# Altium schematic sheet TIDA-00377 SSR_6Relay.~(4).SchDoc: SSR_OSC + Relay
size 431 x 279 mm; Date: Not shown in title block; ApprovedBy: Not shown in title block; CheckedBy: Not shown in title block; Author: Not shown in title block; CompanyName: Not shown in title block; DrawnBy: Jarrod Krebs; Engineer: Not shown in title block; Organization: Not shown in title block; Address1: Not shown in title block; Address2: Not shown in title block; Address3: Not shown in title block; Address4: Not shown in title block; DocumentNumber: 1; Revision: Use project parameter SCH_Rev; SheetNumber: 2; SheetTotal: 3; PageSetup: Record=PageOptions¦CenterHorizontal=True¦CenterVertical=True¦PrintScale=0.62¦XCorrection=1.00¦YCorrection=1.00¦PrintKind=0¦BorderSize=5000000¦LeftOffset=0¦BottomOffset=0¦Orientation=2¦PaperLength=1000¦PaperWidth=1000¦Scale=100¦PaperSource=15¦PrintQuality=-3¦MediaType=1¦DitherType=10¦PrintScaleMode=1¦PaperKind=Letter¦PaperIndex=1
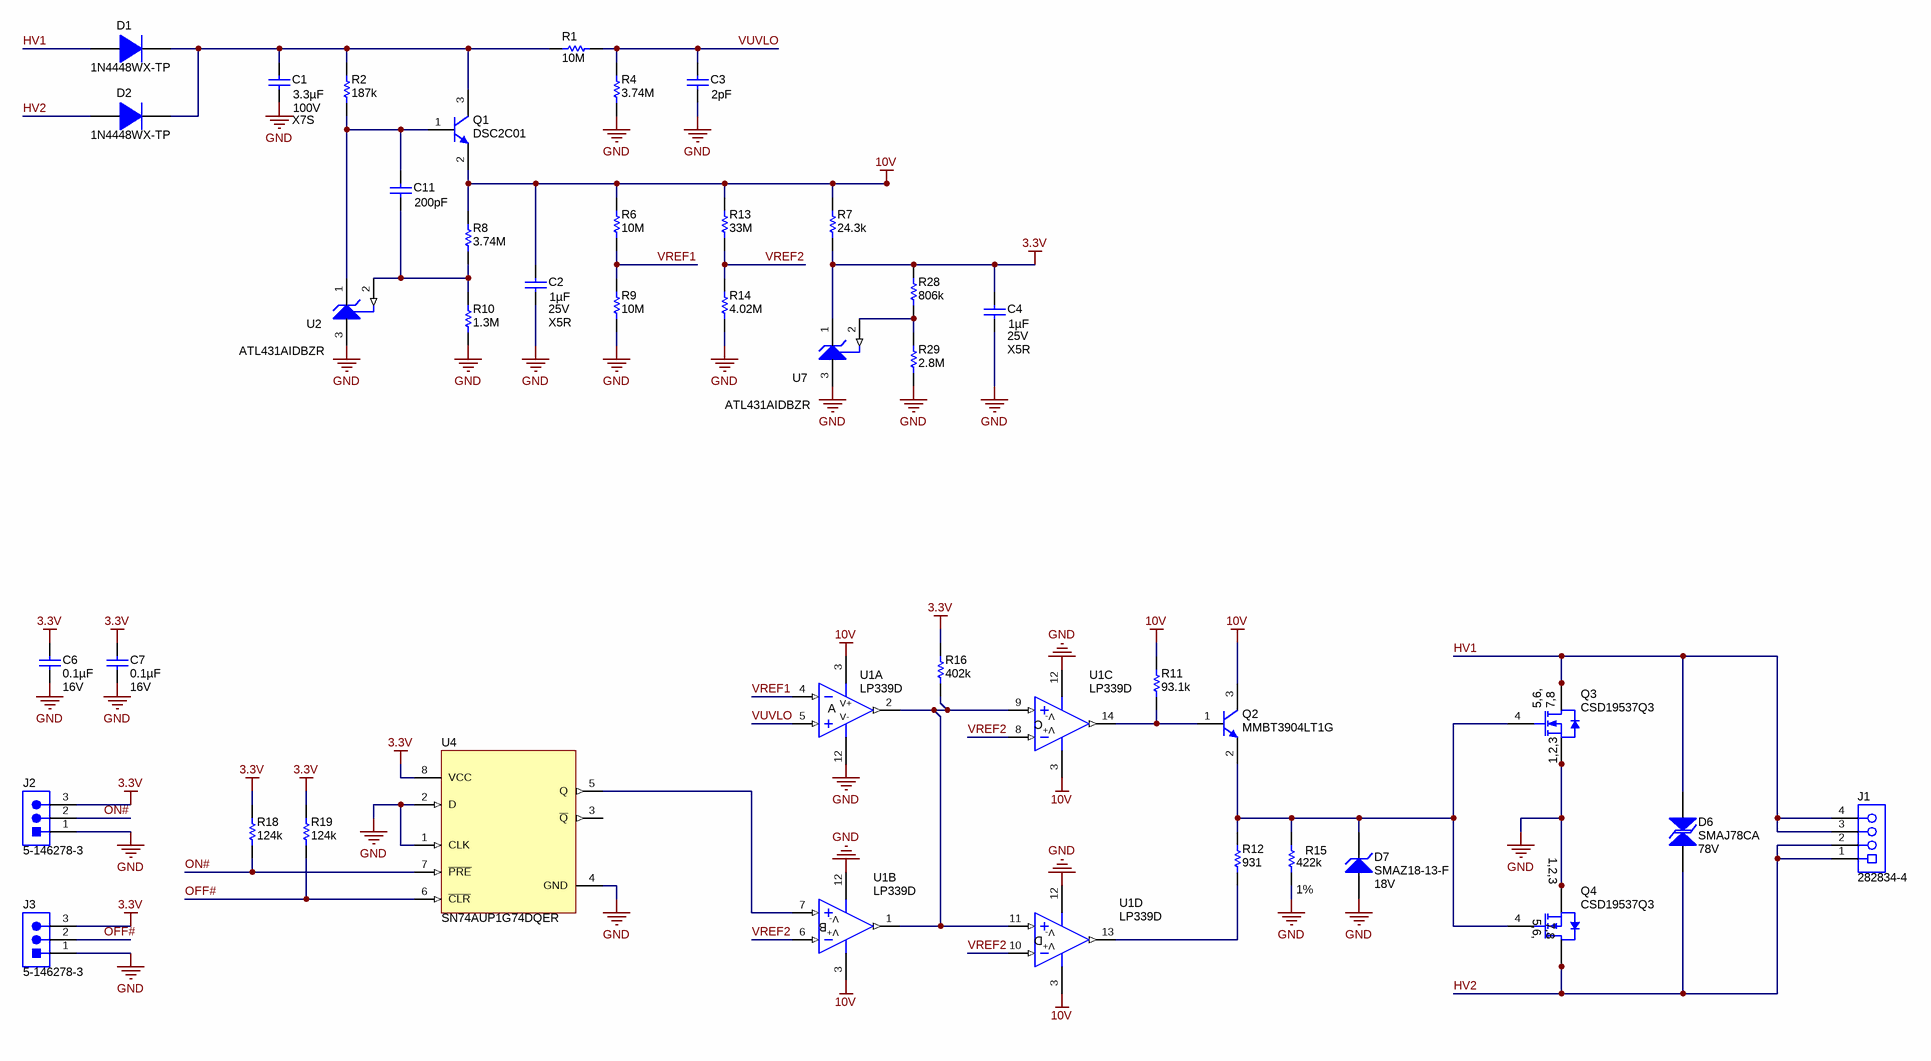
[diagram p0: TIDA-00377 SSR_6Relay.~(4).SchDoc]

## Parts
C1  ValueDisplayed: 3.3µF  VDC_V: 100V  TempCo: X7S  [0603]  (hidden comment: GRM188R61E105KA12D)
C2  ValueDisplayed: 1µF  Value2: 25V  TempCo: X5R  [0603]  (hidden comment: GRM188R61E105KA12D)
C3  ValueDisplayed: 2pF  [0603]  (hidden comment: GRM188R61E105KA12D)
C4  ValueDisplayed: 1µF  Value2: 25V  TempCo: X5R  [0603]  (hidden comment: GRM188R61E105KA12D)
C6  ValueDisplayed: 0.1µF  Value2: 16V  [0603]  (hidden comment: GRM188R71C104KA01D)
C7  ValueDisplayed: 0.1µF  Value2: 16V  [0603]  (hidden comment: GRM188R71C104KA01D)
C11  ValueDisplayed: 200pF  [0603]  (hidden comment: GRM188R61E105KA12D)
D1  1N4448WX-TP  [sod-323]
D2  1N4448WX-TP  [sod-323]
D6  SMAJ78CA  value 78V  [SMA]
D7  SMAZ18-13-F  value 18V  [SMA]
J1  282834-4  [TEC_282834-4]
J2  5-146278-3  [TE_5-146278-3]
J3  5-146278-3  [TE_5-146278-3]
Q1  DSC2C01  [SOT-23]
Q2  MMBT3904LT1G  [SOT-23]
Q3  CSD19537Q3  [DQG0008A]
Q4  CSD19537Q3  [DQG0008A]
R1  ValueDisplayed: 10M  [0805_HV]  (hidden comment: CRCW08050000Z0EA)
R2  ValueDisplayed: 187k  [0805_HV]  (hidden comment: CRCW08050000Z0EA)
R4  ValueDisplayed: 3.74M  [0805_HV]  (hidden comment: CRCW08050000Z0EA)
R6  ValueDisplayed: 10M  [0805_HV]  (hidden comment: CRCW08050000Z0EA)
R7  ValueDisplayed: 24.3k  [0805_HV]  (hidden comment: CRCW08050000Z0EA)
R8  ValueDisplayed: 3.74M  [0805_HV]  (hidden comment: CRCW08050000Z0EA)
R9  ValueDisplayed: 10M  [0805_HV]  (hidden comment: CRCW08050000Z0EA)
R10  ValueDisplayed: 1.3M  [0805_HV]  (hidden comment: CRCW08050000Z0EA)
R11  ValueDisplayed: 93.1k  [0805_HV]  (hidden comment: CRCW08050000Z0EA)
R12  ValueDisplayed: 931  [0805_HV]  (hidden comment: CRCW08050000Z0EA)
R13  ValueDisplayed: 33M  [0805_HV]  (hidden comment: CRCW08050000Z0EA)
R14  ValueDisplayed: 4.02M  [0805_HV]  (hidden comment: CRCW08050000Z0EA)
R15  ValueDisplayed: 422k  Value1: 1%  [0805_HV]  (hidden comment: CRCW0805422KFKEA)
R16  ValueDisplayed: 402k  [0805_HV]  (hidden comment: CRCW08050000Z0EA)
R18  ValueDisplayed: 124k  [0402]  (hidden comment: CRCW0402100KJNED)
R19  ValueDisplayed: 124k  [0402]  (hidden comment: CRCW0402100KJNED)
R28  ValueDisplayed: 806k  [0805_HV]  (hidden comment: CRCW08050000Z0EA)
R29  ValueDisplayed: 2.8M  [0805_HV]  (hidden comment: CRCW08050000Z0EA)
U1  LP339D  [D0014A_N]  (parts A,B,C,D of 4)
U2  ATL431AIDBZR  [DBZ0003A_M]
U4  SN74AUP1G74DQER  [DQE0008A]
U7  ATL431AIDBZR  [DBZ0003A_M]

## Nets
3.3V: C4.2 C6.2 C7.2 J2.3 J3.3 R7.2 R16.1 R18.2 R19.2 R28.1 U4.8(VCC) U7.1(CATHODE)
10V: C2.2 Q1.2(E) Q2.3(C) R6.1 R7.1 R8.1 R11.1 R13.1 U1.3(V+)
GND: C1.1 C2.1 C3.1 C4.1 C6.1 C7.1 D7.2(A) J2.1 J3.1 Q3.1(S) Q3.2(S) Q3.3(S) Q4.1(S) Q4.2(S) Q4.3(S) R4.2 R9.2 R10.2 R14.2 R15.1 R29.2 U1.12(V-) U2.3(ANODE) U4.1(CLK) U4.2(D) U4.4(GND) U7.3(ANODE)
HV1: D1.2(A) D6.2 J1.3 J1.4 Q3.5(D) Q3.6(D) Q3.7(D) Q3.8(D) Q3.9(D)
HV2: D2.2(A) D6.1 J1.1 J1.2 Q4.5(D) Q4.6(D) Q4.7(D) Q4.8(D) Q4.9(D)
OFF#: J3.2 R19.1 U4.6(~{CLR})
ON#: J2.2 R18.1 U4.7(~{PRE})
VREF1: R6.2 R9.1 U1.4(-IN1)
VREF2: R13.2 R14.1 U1.6(-IN2) U1.8(-IN3) U1.10(-IN4)
VUVLO: C3.2 R1.2 R4.1 U1.5(+IN1)
NetC1_2: C1.2 D1.1(K) D2.1(K) Q1.3(C) R1.1 R2.1
NetC11_1: C11.1 R8.2 R10.1 U2.2(REF)
NetC11_2: C11.2 Q1.1(B) R2.2 U2.1(CATHODE)
NetD7_1: D7.1(K) Q2.2(E) Q3.4(G) Q4.4(G) R12.2 R15.2
NetQ2_1: Q2.1(B) R11.2 U1.14(OUT3)
NetR12_1: R12.1 U1.13(OUT4)
NetR16_2: R16.2 U1.1(OUT2) U1.2(OUT1) U1.9(+IN3) U1.11(+IN4)
NetR28_2: R28.2 R29.1 U7.2(REF)
NetU1_7: U1.7(+IN2) U4.5(Q)

Not connected (* = marked no-connect by the designer): U4 3(~{Q})

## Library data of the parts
C1 = GRM188R61E105KA12D: CAP, CERM, 3.3 µF, 100 V, +/- 10%, X5R, 0603; Manufacturer: MuRata; Polarized: N; CompType: Capacitor; Value: 1uF; U/M: EA; Cap_F: 0.000001; Tolerance_%: 10; Value1: Unknown; TaMin_C: -55; TaMax_C: 85; AEC Category: Q200
C2 C4 = GRM188R61E105KA12D: CAP, CERM, 1 µF, 25 V, +/- 10%, X5R, 0603; Manufacturer: MuRata; Polarized: N; CompType: Capacitor; Value: 1uF; U/M: EA; Cap_F: 0.000001; Tolerance_%: 10; Value1: Unknown; VDC_V: 25; TaMin_C: -55; TaMax_C: 85; AEC Category: Q200
C3 C11 = GRM188R61E105KA12D: CAP, CERM, 1 µF, 25 V, +/- 10%, X5R, 0603; Manufacturer: MuRata; Polarized: N; CompType: Capacitor; Value: 1uF; U/M: EA; Cap_F: 0.000001; Tolerance_%: 10; Value1: Unknown; VDC_V: 25; Value2: 25V; TaMin_C: -55; TaMax_C: 85; AEC Category: Q200
C6 C7 = GRM188R71C104KA01D: CAP, CERM, 0.1 µF, 16 V, +/- 10%, X7R, 0603; Manufacturer: MuRata; Polarized: N; CompType: Capacitor; Value: 0.1uF; U/M: EA; Cap_F: 0.0000001; Tolerance_%: 10; Value1: Unknown; VDC_V: 16; TaMin_C: -55; TaMax_C: 125; AEC Category: Q200
D1 D2 = 1N4448WX-TP: Diode, Switching, 75 V, 0.25 A, SOD-323; Manufacturer: Micro Commercial Components; U/M: EA; Value: 75V; Value1: 0.25A; Io_A: 0.25; Vr_V: 75; TJmax_C: 150; AEC Category: Q101
D6 = SMAJ78CA: Diode, TVS, Bi, 78 V, 400 W, SMA; Manufacturer: Littelfuse; U/M: EA; Power_W: 400; Vr_V: 78; Value1: 400W; RJA_CperW: 120; AEC Category: Q101
D7 = SMAZ18-13-F: Diode, Zener, 18 V, 1 W, AEC-Q101, SMA; Manufacturer: Diodes Inc.; SymbolCreator: a0412235; U/M: EA; Power_W: 1; Vz_V: 18; Value1: 1W; RJA_CperW: 125; AEC Category: Q101; AEC Qualified: Y
J1 = 282834-4: Terminal Block, 100mil, 4X1 TH; Manufacturer: TE Connectivity; SymbolCreator: a0411947
J2 J3 = 5-146278-3: Header, 100mil, 3x1, Tin, TH; Manufacturer: TE Connectivity; SymbolCreator: a0799628
Q1 = MMBT2222A, Fairchild Semiconductor: Transistor, NPN, 40 V, 0.15 A, SOT-23; CompType: BJT; PNP: 0; NPN: 1; Vceo_V: 40; Vcesat1_V: 0.3; Value: 40 V; IcRated_A: 0.15; Value1: 0.15 A; HfeMax: 300; TaMin_C: -55; TaMax_C: 150; U/M: EA; AEC Category: Q101
Q2 = MMBT3904LT1G, ON Semiconductor: Transistor, NPN, 40 V, 0.2 A, SOT-23; CompType: BJT; PNP: 0; NPN: 1; Vceo_V: 40; Vcesat1_V: 0.3; Value: 40 V; IcRated_A: 0.2; Value1: 0.2 A; HfeMax: 300; TaMin_C: -55; TaMax_C: 150; U/M: EA; AEC Category: Q101
Q3 Q4 = CSD19537Q3: MOSFET, N-CH, 100 V, 50 A, DQG0008A; Manufacturer: Texas Instruments; Alternate Manufacturer: None; U/M: EA; ChType: N; Value: 100V; VdsMax_V: 100; Value1: ? ohm; Value2: 16 nC; QgTyp_nC: 16; Vgs_V: 20; IdsMax_A: 50; AEC Category: Q101
R1 R2 R4 R6-R14 R16 R28 R29 = CRCW08050000Z0EA: RES, 0, 5%, 0.125 W, 0805; Manufacturer: Vishay-Dale; CompType: Resistor; Value: 0; Value_Code: 0000; Tolerance_%: 5; Power_W: 0.125; Value2: 0.125W; VDC_V: 150; TempCo: 200 ppm/C; EIA_Code: E24; U/M: EA; AEC Category: Q200
R15 = CRCW0805422KFKEA: RES, 422 k, 1%, 0.125 W, 0805; Manufacturer: Vishay-Dale; CompType: Resistor; Value: 422k; Res_ohm: 422000; Tolerance_%: 1; Power_W: 0.125; Value2: 0.125W; VDC_V: 150; TempCo: 100 ppm/C; EIA_Code: E96; U/M: EA; AEC Category: Q200
R18 R19 = CRCW0402100KJNED: RES, 100 k, 5%, 0.063 W, 0402; Manufacturer: Vishay-Dale; CompType: Resistor; Value: 100k; Res_ohm: 100000; Tolerance_%: 5; Power_W: 0.063; Value2: 0.063W; VDC_V: 50; TempCo: 200 ppm/C; EIA_Code: E24; U/M: EA; AEC Category: Q200
U1 = LP339D: Quad, Low-Power, General Purpose Differential Comparator, D0014A; Manufacturer: Texas Instruments; SymbolCreator: Altium; CompType: OpAmp IC
U2 U7 = ATL431AIDBZR: 2.5V Low Iq Adjustable Precision Shunt Regulator, DBZ0003A; Manufacturer: Texas Instruments; SymbolCreator: a0412235; CompType: IC; U/M: EA
U4 = SN74AUP1G74DQER: LOW-POWER SINGLE POSITIVE-EDGE-TRIGGERED D-TYPE FLIP-FLOP WITH CLEAR AND PRESET, DQE0008A; Manufacturer: Texas Instruments; SymbolCreator: a0799628; CompType: IC; U/M: EA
